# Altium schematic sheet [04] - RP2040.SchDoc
size A3; DocumentNumber: 4; SheetNumber: 4; SheetTotal: 4
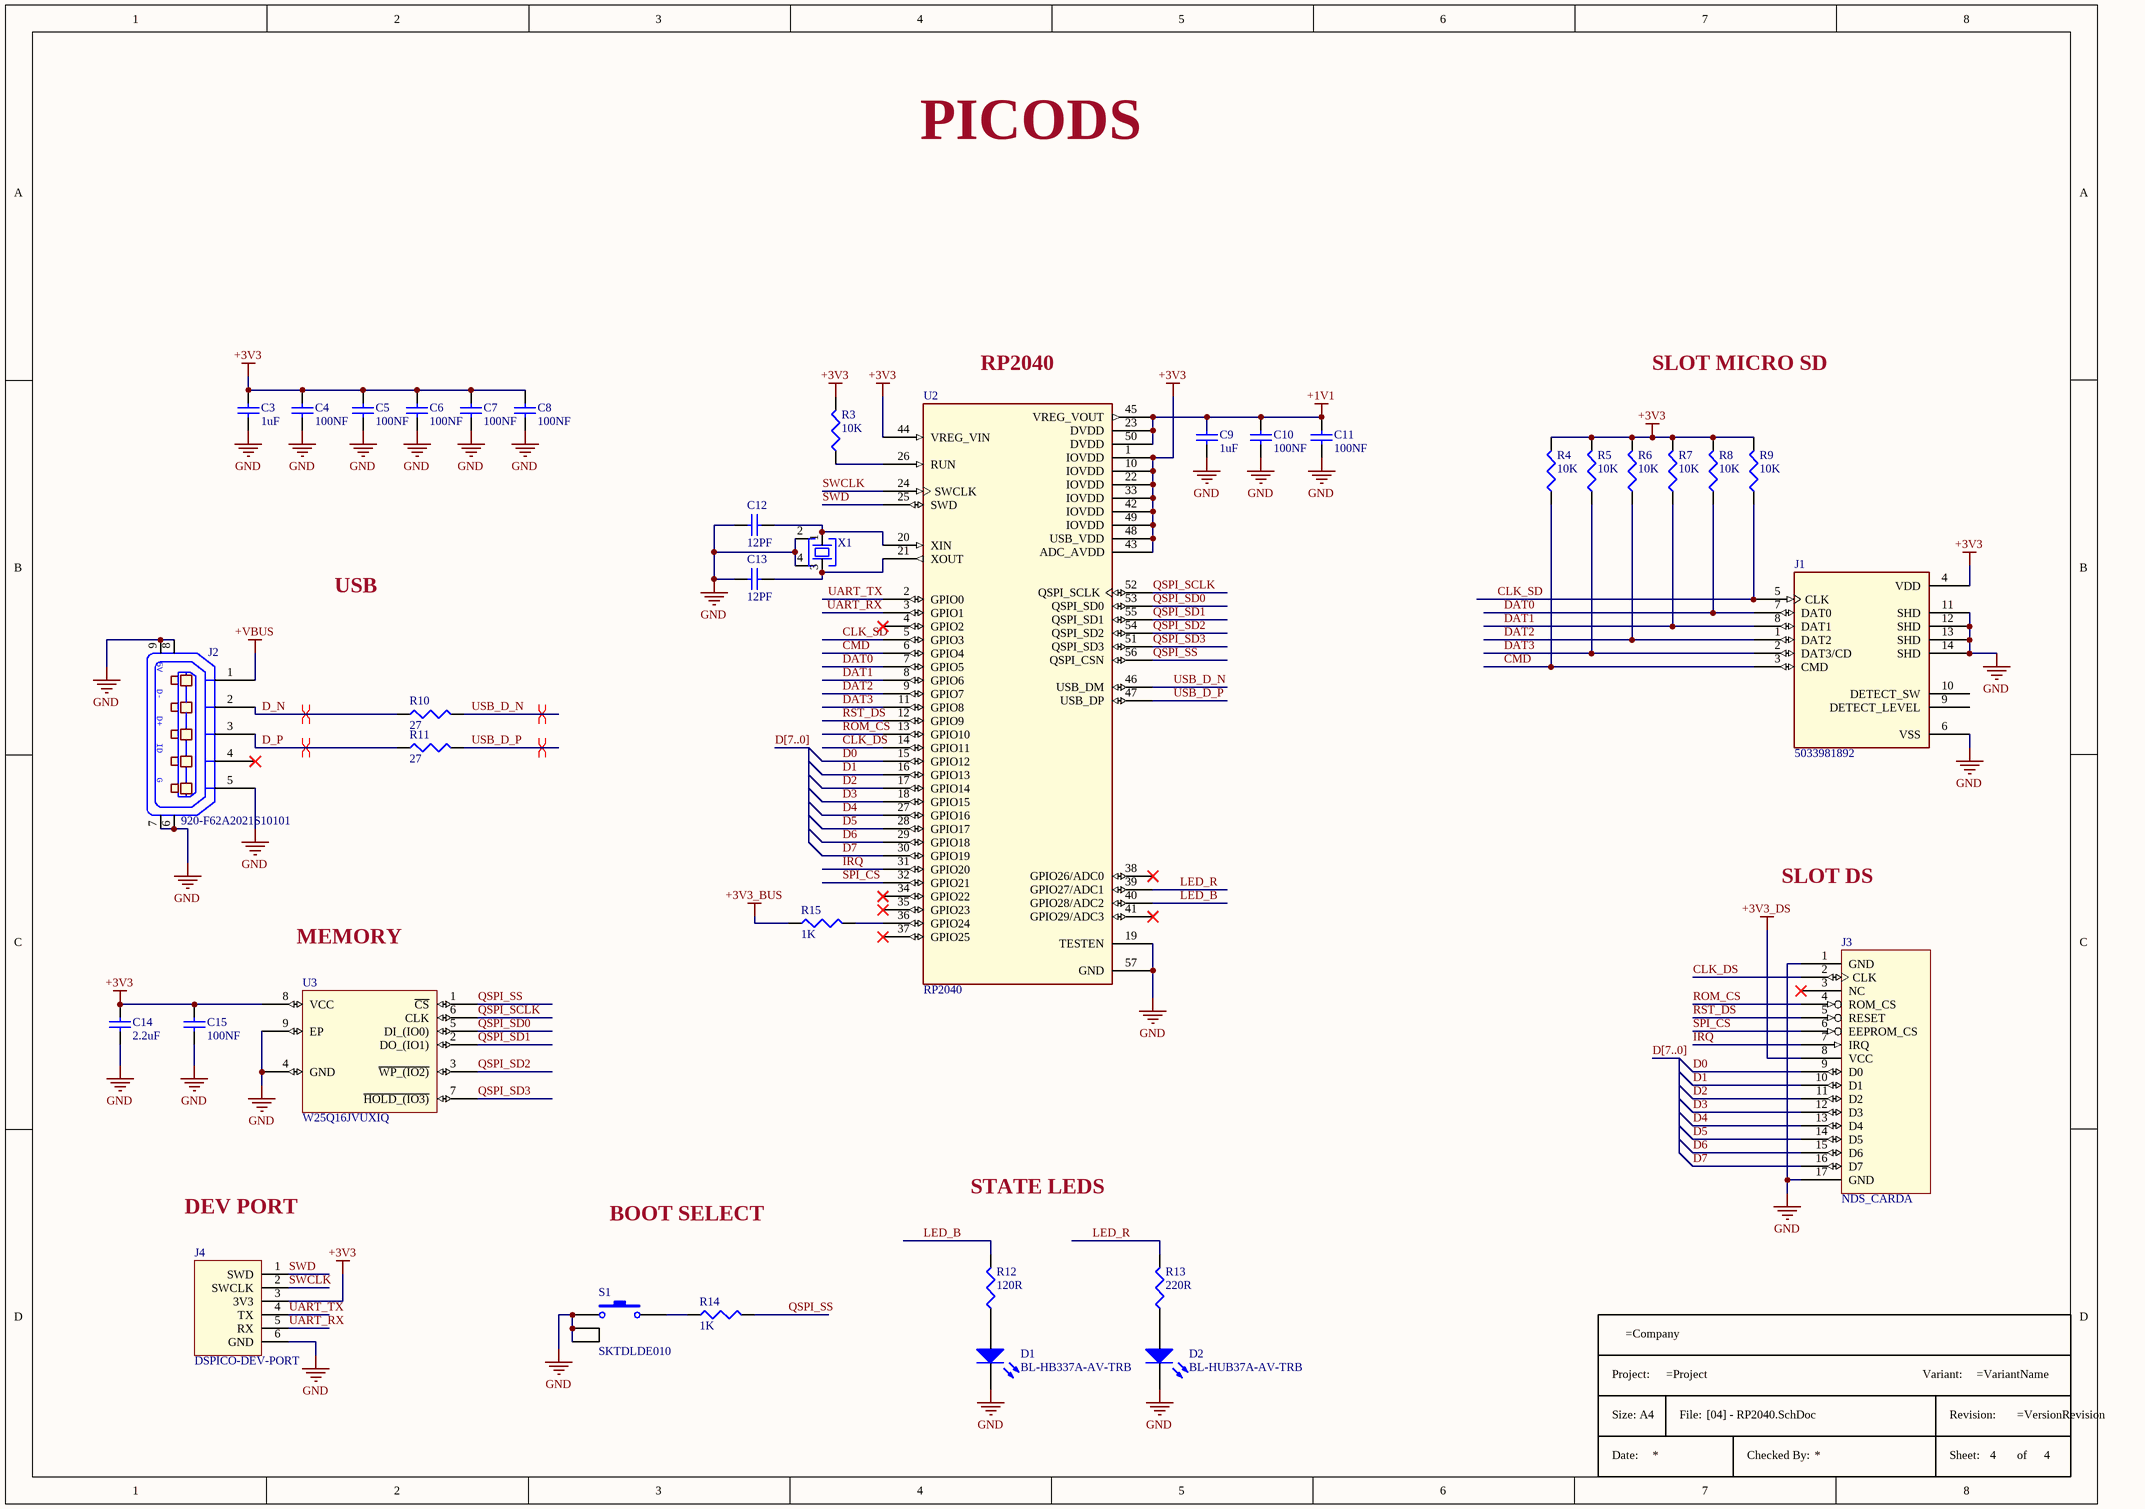
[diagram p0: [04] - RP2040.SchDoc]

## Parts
*  Title Block A4  (value not drawn)  (graphical)
C3  1uF  [C0402]
C4  100NF  [C0402]
C5  100NF  [C0402]
C6  100NF  [C0402]
C7  100NF  [C0402]
C8  100NF  [C0402]
C9  1uF  [C0402]
C10  100NF  [C0402]
C11  100NF  [C0402]
C12  12PF  [C0402]
C13  12PF  [C0402]
C14  2.2uF  [C0402]
C15  100NF  [C0402]
D1  BL-HB337A-AV-TRB  [LED0402-RD]
D2  BL-HUB37A-AV-TRB  [LED0402-RD]
J1  5033981892  [503398-1892_MOL]
J2  920-F62A2021S10101  [MICRO-USB_MICRO-USB-31]
J3  NDS_CARDA  [NDS_CARD]  (no BOM)
J4  DSPICO-DEV-PORT  [EP_DEV_PORT]  (no BOM)
R3  10K  [R0402]
R4  10K  [R0402]
R5  10K  [R0402]
R6  10K  [R0402]
R7  10K  [R0402]
R8  10K  [R0402]
R9  10K  [R0402]
R10  value 27  [R0402]  (hidden comment: RC0402FR-0727RL)
R11  value 27  [R0402]  (hidden comment: RC0402FR-0727RL)
R12  120R  [R0402]
R13  220R  [R0402]
R14  1K  [R0402]
R15  1K  [R0402]
S1  SKTDLDE010  [KEY-SMD_SKTDLDE010]
U2  RP2040  [QFN40P700X700X90-57N]
U3  W25Q16JVUXIQ  [SON50P300X200X60-9N]
X1  XYDBPCNANF-12MHZ  [OSC-SMD_4P-L2.5-W2.0-BL]  (value not drawn)

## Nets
+1V1: C9.2 C10.2 C11.2 U2.23(DVDD) U2.45(VREG_VOUT) U2.50(DVDD)
+3V3: C3.2 C4.2 C5.2 C6.2 C7.2 C8.2 C14.2 C15.2 J1.4(VDD) J4.3(3V3) R3.2 R4.2 R5.2 R6.2 R7.2 R8.2 R9.2 U2.1(IOVDD) U2.10(IOVDD) U2.22(IOVDD) U2.33(IOVDD) U2.42(IOVDD) U2.43(ADC_AVDD) U2.44(VREG_VIN) U2.48(USB_VDD) U2.49(IOVDD) U3.8(VCC)
+3V3_BUS: R15.1
+3V3_DS: J3.8(VCC)
+VBUS: J2.1(P1)
GND: C3.1 C4.1 C5.1 C6.1 C7.1 C8.1 C9.1 C10.1 C11.1 C12.1 C13.1 C14.1 C15.1 D1.1 D2.1 J1.6(VSS) J1.11(SHD) J1.12(SHD) J1.13(SHD) J1.14(SHD) J2.5(P5) J2.6 J2.7 J2.8 J2.9 J3.1(GND) J3.17(GND) J4.6(GND) S1.1 S1.3 S1.4 U2.19(TESTEN) U2.57(GND) U3.4(GND) U3.9(EP) X1.2 X1.4
CLK_DS: J3.2(CLK) U2.14(GPIO11)
CLK_SD: J1.5(CLK) R9.1 U2.5(GPIO3)
CMD: J1.3(CMD) R4.1 U2.6(GPIO4)
D0: J3.9(D0) U2.15(GPIO12)
D1: J3.10(D1) U2.16(GPIO13)
D2: J3.11(D2) U2.17(GPIO14)
D3: J3.12(D3) U2.18(GPIO15)
D4: J3.13(D4) U2.27(GPIO16)
D5: J3.14(D5) U2.28(GPIO17)
D6: J3.15(D6) U2.29(GPIO18)
D7: J3.16(D7) U2.30(GPIO19)
D_N: J2.2(P2) R10.1
D_P: J2.3(P3) R11.1
DAT0: J1.7(DAT0) R8.1 U2.7(GPIO5)
DAT1: J1.8(DAT1) R7.1 U2.8(GPIO6)
DAT2: J1.1(DAT2) R6.1 U2.9(GPIO7)
DAT3: J1.2(DAT3/CD) R5.1 U2.11(GPIO8)
IRQ: J3.7(IRQ) U2.31(GPIO20)
LED_B: R12.2 U2.40(GPIO28/ADC2)
LED_R: R13.2 U2.39(GPIO27/ADC1)
QSPI_SCLK: U2.52(QSPI_SCLK) U3.6(CLK)
QSPI_SD0: U2.53(QSPI_SD0) U3.5(DI_(IO0))
QSPI_SD1: U2.55(QSPI_SD1) U3.2(DO_(IO1))
QSPI_SD2: U2.54(QSPI_SD2) U3.3(~{WP_(IO2)})
QSPI_SD3: U2.51(QSPI_SD3) U3.7(~{HOLD_(IO3)})
QSPI_SS: R14.2 U2.56(QSPI_CSN) U3.1(~{CS})
ROM_CS: J3.4(ROM_CS) U2.13(GPIO10)
RST_DS: J3.5(RESET) U2.12(GPIO9)
SPI_CS: J3.6(EEPROM_CS) U2.32(GPIO21)
SWCLK: J4.2(SWCLK) U2.24(SWCLK)
SWD: J4.1(SWD) U2.25(SWD)
UART_RX: J4.5(RX) U2.3(GPIO1)
UART_TX: J4.4(TX) U2.2(GPIO0)
USB_D_N: R10.2 U2.46(USB_DM)
USB_D_P: R11.2 U2.47(USB_DP)
NetC12_2: C12.2 U2.20(XIN) X1.1
NetC13_2: C13.2 U2.21(XOUT) X1.3
NetD1_2: D1.2 R12.1
NetD2_2: D2.2 R13.1
NetR3_1: R3.1 U2.26(RUN)
NetR14_1: R14.1 S1.2
NetR15_2: R15.2 U2.36(GPIO24)

Not connected (* = marked no-connect by the designer): J1 9(DETECT_LEVEL) 10(DETECT_SW); J2 4(P4)*; J3 3(NC)*; U2 4(GPIO2)* 34(GPIO22)* 35(GPIO23)* 37(GPIO25)* 38(GPIO26/ADC0)* 41(GPIO29/ADC3)*

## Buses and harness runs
bus D[7..0]

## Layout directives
differential pair: D_N, D_P, USB_D_N, USB_D_P

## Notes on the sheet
- PICODS
- (near U2) RP2040
- SLOT MICRO SD
- USB
- SLOT DS
- MEMORY
- DEV PORT
- BOOT SELECT
- STATE LEDS

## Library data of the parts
C3 C9 = C1005X5R1E105K050BC: TDK - C1005X5R1E105K050BC - COND, CERÁ MULT, X5R, 1UF, 25V, 0402; Dielectric Material: Ceramic; Tolerance: 10%
C4-C8 C10 C11 C15 = GRM155R71C104KA88D: 0402 0.1 uF 16V ±10 % Tolerance X7R SMT Multilayer Ceramic Capacitor; Manufacturer: Murata; Tolerance: 10%; Insulation Resistance: 10GR
C12 C13 = 04025A120JAT2A: CAP CER 12PF 50V C0G/NP0 0402; Manufacturer: Kyocera AVX; Tolerance: 5%; Dielectric: C0G; Temperature Coefficient: 30ppm/°C; Insulation Resistance: 100GR
C14 = C1005X5R1A225K050BC: TDK - C1005X5R1A225K050BC - COND, CERÁ MULT, X5R, 2.2UF, 10V, 0402; .PCBCheck: VMM
D1 = BL-HB337A-AV-TRB: Blue 0402 1X.5X4MM; Manufacturer: American Bright; Lens Color: Colorless; Lens Style: Flat; Lens Transparency: Clear; Luminous Intensity: 35mcd; Forward Voltage: 2.8V; Test Current: 20mA; Viewing Angle: 120°; Dominant Wavelength: 571nm; Lens Size: 0.5mm
D2 = BL-HUB37A-AV-TRB: Red 0402 1X.5X4MM; Manufacturer: American Bright; Lens Color: Colorless; Lens Style: Flat; Lens Transparency: Clear; Luminous Intensity: 35mcd; Forward Voltage: 2V; Test Current: 20mA; Viewing Angle: 120°; Dominant Wavelength: 571nm; Lens Size: 0.5mm
J3 = NDS_CARDA: SymbolName_1: NDS_CONNECTOR; DeviceName: A
J4 = PICO-DEVELOP-PORT: DSpico Development port; Manufacturer: LNH; Number of Positions: 6; Connector Type: Outer Shroud Contact; Voltage Rating: 3.3V; Gender: Male; Pitch: 2.54; Wire/Cable Gauge: 26AWG
R3-R9 = CRCW040210K0FKED: VISHAY DRALORIC - CRCW040210K0FKED - RESISTENCIA, 10K, 0.063W, 1%, 0402, SMD; Resistance: 10kR; Temperature Coefficient: 100ppm/°C; Power Rating: 63mW; Voltage Rating: 50V
R10 R11 = RC0402FR-0727RL: RES 27 OHM 1% 1/16W 0402; Package Height: 0.35mm; Rated Power Dissipation (P): 62.5mW; Rated Temperature: 70°C; Additional Feature: LASER TRIMMABLE; Resistance: 27R; Package Length: 1mm; Temperature Coefficient: 100ppm/°C; Package Width: 0.5mm; Working Voltage: 50V
R12 = RC0402FR-07120RL: Res General Purpose Thick Film 0402 120 Ohm 1% 1/16W ±100ppm/°C Molded Paper T/R; Manufacturer: Yageo; Voltage Rating: 50V; Power Rating: 62.5mW; Max Power Dissipation: 63mW
R13 = RC0402FR-07220RL: SMD Chip Resistor, 220 Ohm, ± 1%, 62.5 mW, 0402 [1005 Metric], Thick Film, General Purpose; Manufacturer: Yageo; Voltage Rating: 50V; Power Rating: 62.5mW; Max Power Dissipation: 63mW; Temperature Coefficient: 100ppm/°C
R14 R15 = CRCW04021K00FKEDC: VISHAY - CRCW04021K00FKED - RES, PELÍC GRUESA, 1K, 1%, 0.063W, 0402; Resistencia: 1; Tensión Nominal: 50; Tipo de Resistencia: 0402 [Métrica 1005]; Potencia Nominal: 63; Rango de Producto: Serie AEC-Q200 CRCW; Encapsulado: Cinta Cortada; Tipo de Elemento Resistivo: Película Gruesa; Coeficiente de Temperatura: ± 100; Estándar de Certificación para Automoción: AEC-Q200; Nivel de Sensibilidad a la Humedad (MSL): MSL 1 - Ilimitado; Núm. de Contactos Macho: 2; Rango de Temperatura de Funcionamiento: -55°C a +155; Resistencia, Montaje: Dispositivo de Montaje Superficial (SMD); Temperatura de Trabajo Máx.: 155; Temperatura de Trabajo Mín.: -55°C<!--FANDB--><div class="features-and-benefits-container"><div class="features-and-benefits-description"><span class="features-benefits-value">The Vishay D/CRCW e3 series are standard thick film chip resistors. The resistance range includes E96 and E24 decade values from 1ohm to 10Mohm. CRCW e3 series resistors have a pure tin solder contacts on the Ni barrier layer that provides compatibility with reflow soldering process.</span></div><div class="features-and-benefits-list"><ul class="features-and-benefits-list-list"><li class="features-and-benefits-list-item">Automotive grade AEC-Q200 qualified</li><li class="features-and-benefits-list-item">EIA 0402, 0603, 0805, 1206, 1210, 1218, 2010, 2512 standard case sizes available</li><li class="features-and-benefits-list-item">Stability &Delta
S1 = SKTDLDE010: Switch Tactile N.O. SPST Rectangular Button Gull Wing 0.05A 12VDC 1.6N SMD T/R; Manufacturer: Alps Electric
U2 = RP2040: RP2040 chip for Raspberry Pi Pico - ARM Cortex-M0+ MCU 32-Bit
U3 = W25Q16JVUXIQ: NOR Flash Serial (SPI, Dual SPI, Quad SPI) 3V/3.3V 16M-bit 2M x 8 6ns 8-Pin USON EP T/R; MF: Winbond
